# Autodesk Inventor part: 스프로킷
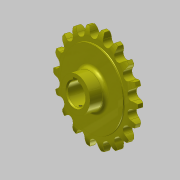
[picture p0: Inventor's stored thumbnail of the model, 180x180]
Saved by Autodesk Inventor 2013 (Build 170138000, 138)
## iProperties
Created: 2016-03
Part Number: 스프로킷
Material: 강철, 탄소
Document SubType Name: Modeling
Designer: mduedu
Density: 7.87 g/cm^3
Mass: 299.992 g
Surface Area: 127.848 cm^2
Volume: 38.1184 cm^3
Author: mduedu
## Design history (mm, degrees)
sketch "스케치1"
  geometry: L1 (0, 5)-(29.5, 5); L2 (29.5, 5)-(29.5, 4.1); L3 (30, 3.6)-(33.625, 3.6); L4 (40, 2)-(40, 0); L5 (40, 0)-(0, 0); L6 (0, 0)-(0, 5); L7 (0, -5)-(29.5, -5); L8 (29.5, -5)-(29.5, -4.1); L9 (30, -3.6)-(33.625, -3.6); L10 (40, -2)-(40, 0); L11 (0, 0)-(0, -5); A1 r 13.5 centre (33.625, -9.9) between (40, 2) and (33.625, 3.6); A2 r 13.5 centre (33.625, 9.9) between (33.625, -3.6) and (40, -2); A3 r 0.5 centre (30, 4.1) between (29.5, 4.1) and (30, 3.6); A4 r 0.5 centre (30, -4.1) between (30, -3.6) and (29.5, -4.1); 2 further points
  constraints: 22 end point, 8 point on circle, 6 symmetric about line, 5 tangent, 4 centre point, 4 parallel, 4 point on line, 1 equal radius, 1 horizontal, 1 perpendicular, 1 other
  dimensions: "d0" = 80 diameter of L4 L6; "d2" = 59 diameter of L2 L6; "d3" = 1.6 vertical distance of L4.start L3.end; "d4" = 3.6 distance from line of L4.end L3; "d5" = 5 distance between parallel lines of L5 L1; "d6" = 13.5 radius of A1; "d15" = 0.5 radius of A3
revolve "회전1" sketch "스케치1" stored, may be unused: angle "d7" = 90 deg
sketch "스케치2" dims "d8" = 65.2, "d11" = 80
  geometry: L1 (0, 0)-(0, 32.6); A1 r 36.57 centre (0, 0) between (-16.231, 32.771) and (0, 36.57); A2 r 3.97 centre (0, 36.57) between (-3.866, 35.665) and (0, 32.6); A3 r 12.7 centre (-16.231, 32.771) between (-3.866, 35.665) and (-5.534, 39.615); A4 r 12.7 centre (16.231, 32.771) between (5.534, 39.615) and (3.866, 35.665); A5 r 3.97 centre (0, 36.57) between (0, 32.6) and (3.866, 35.665); A6 r 40 centre (0, 0) between (5.534, 39.615) and (-5.534, 39.615); 2 further points
  constraints: 12 point on circle, 6 centre point, 4 coincident, 3 symmetric about line, 2 end point, 1 point on line, 1 tangent, 1 vertical, 1 vertical alignment, 7 other
  dimensions: "d10" = 73.14 diameter of A1; "d12" = 12.7 radius of A3
extrude "돌출1" cut sketch "스케치2" stored distance "d13" = 10; taper "d14" = 0 deg
sketch "스케치3"
  geometry: C1 r 13.5 at (0, 0); 1 further point
  constraints: 1 centre point, 1 coincident
  dimensions: "d19" = 27 diameter of C1
extrude "돌출2" join sketch "스케치3" distance "d20" = 13; taper "d21" = 0 deg
fillet "모깎기1" dims "d22" = 3
sketch "스케치4"
  geometry: L1 (-2.5, 0)-(2.5, 0); L2 (2.5, 0)-(2.5, 10.8); L3 (2.5, 10.8)-(-2.5, 10.8); L4 (-2.5, 10.8)-(-2.5, 0); C1 r 8.5 at (0, 0); 2 further points
  constraints: 8 end point, 2 coincident, 2 parallel, 1 centre point, 1 horizontal, 1 midpoint, 1 perpendicular
  dimensions: "d23" = 17 diameter of C1; "d25" = 5 distance of L2.end L3.end; "d26" = 10.8 distance of L1.end L2.end
extrude "돌출3" cut sketch "스케치4" stored distance "d27" = 8; taper "d28" = 0 deg
chamfer "모따기1" distance "d29" = 1; stored, may be unused: second distance "d30" = 2, angle "d31" = 45 deg
node "작업 평면1"
sketch "스케치5"
  geometry: L1 (13.5, 13)-(-13.5, 13) reference; 2 further points
  constraints: 1 vertical alignment
  dimensions: "d32" = 4 distance from line of point (0, 9) L1
hole "구멍1" sketch "스케치5" at (0, 9) diameter "d33" = 2.459; stored, may be unused: countersink angle "d37" = 90 deg, drill point angle "d39" = 118 deg; dims "d34" = 6, "d35" = 4, "d36" = 2, "d38" = 8
node "솔리드1"
pattern_circular "원형 패턴1" dims angle "d17" = 360 deg
